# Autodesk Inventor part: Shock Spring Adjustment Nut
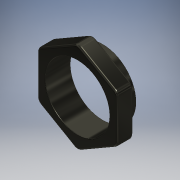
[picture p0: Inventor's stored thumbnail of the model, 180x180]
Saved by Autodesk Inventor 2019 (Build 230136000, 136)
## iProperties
Shininess: 50.0
Compacted: True
Length Units: 11272
Angle Units: 11279
Time Units: 11290
Mass Units: 11286
Length Display Precision: 4
Angle Display Precision: 2
Company: Autodesk
Created: 2000-03
Part Number: Shock Spring Adjustment Nut
Project: Inventor Samples
User Status: IN PROGRESS
Document SubType Name: Modeling
Designer: Autodesk, Inc.
Density: 1.13 g/cm^3
Mass: 0.350545 g
Surface Area: 6.09851 cm^2
Volume: 0.310217 cm^3
Material: Nylon-6/6
Appearance: Gunmetal
Density: 0.0
Volumn: 0.0
Area: 0.0
PropertySet Name: Model Information
Control State: 0
Master: False
Checked Out: False
Checked Out Date: 2018-05-30
Last Check In Date: 2018-05-30
Author: Autodesk, Inc.
Revision Number: A
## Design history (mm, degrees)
node "Extrusion1" dims "d1" = 1.905, "d2" = 0
  sketch "Sketch2"
    geometry: C1 r 6.668 at (-5.692, -2.081)
    constraints: 1 centre point
    dimensions: "d0" = 13.335 diameter of C1
node "Extrusion2" dims "d4" = 3.175, "d5" = 0
  sketch "Sketch3"
    geometry: L1 (-7.938, -4.583)-(-7.938, 4.583); L2 (-7.938, 4.583)-(0, 9.165); L3 (0, 9.165)-(7.938, 4.583); L4 (7.938, 4.583)-(7.938, -4.583); L5 (7.938, -4.583)-(0, -9.165); L6 (0, -9.165)-(-7.938, -4.583); C1 r 7.938 at (0, 0); C2 r 6.668 at (0, 0) reference
    constraints: 12 end point, 6 tangent, 4 equal length, 1 centre point, 1 concentric, 1 parallel, 1 vertical
    dimensions: "d3" = 15.875 diameter of C1
node "Extrusion3" dims "d7" = 3.175, "d8" = 0
  sketch "Sketch4"
    geometry: C1 r 6.35 at (0, 0); C2 r 6.668 at (0, 0) reference
    constraints: 1 centre point, 1 coincident
    dimensions: "d6" = 12.7 diameter of C1
node "Fillet1" dims "d9" = 1.27
node "Fillet2" dims "d10" = 0.381, "d11" = 0.127
body "Solid1"
